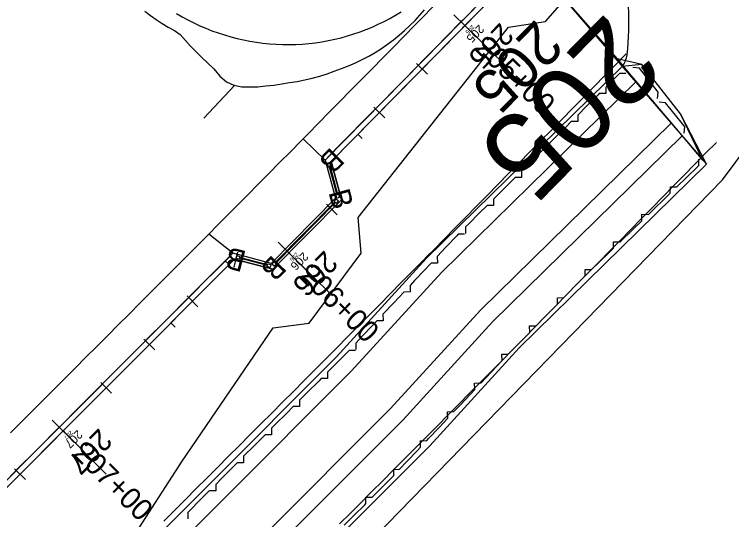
# Model space of a CAD drawing. Extents: x 1823824 to 1861612, y 706975 to 726130.
# Drawn here: x 1824906.5 to 1825141.5, y 712089.6 to 712255.1 of the extents above; entities that cross this region are included whole.
import ezdxf

# ---------------------------------------------------------------- set-up
doc = ezdxf.new("R2010")
doc.units = 0
for name, color, linetype in [('DR_X_Flood_Boundary', 7, 'Continuous'), ('GE_X_CL_10', 7, 'Continuous'), ('GE_X_CL_100', 7, 'Continuous'), ('GE_X_CL_20', 7, 'Continuous'), ('GE_X_CL_200', 7, 'Continuous'), ('GE_X_CL_50', 7, 'Continuous'), ('RW_X_Esmt_FL', 7, 'Continuous'), ('SC_Scratch1', 7, 'Continuous'), ('SC_Scratch3', 7, 'Continuous'), ('SC_Scratch5', 7, 'Continuous'), ('SC_Scratch6', 7, 'Continuous')]:
    doc.layers.add(name, color=color, linetype=linetype)

msp = doc.modelspace()

# ---------------------------------------------------------------- linework, layer by layer
at = {"layer": 'DR_X_Flood_Boundary'}
for p, q in [((1825073.72, 712271.49), (1825010.26, 712206.92)), ((1825010.26, 712206.92), (1825013.68, 712194.38)), ((1825013.68, 712194.38), (1824991.17, 712171.64)), ((1824978.6, 712174.93), (1824894.12, 712090.29)), ((1824991.17, 712171.64), (1824978.6, 712174.93))]:
    msp.add_line(p, q, dxfattribs=at)
at = {"layer": 'GE_X_CL_10'}
for p, q in [((1825054.1, 712251.52), (1825054.81, 712250.82)), ((1825019.05, 712215.86), (1825019.76, 712215.16)), ((1824996.47, 712177), (1824997.19, 712176.29)), ((1824957.78, 712154.08), (1824958.49, 712153.37)), ((1824922.46, 712118.69), (1824923.17, 712117.98))]:
    msp.add_line(p, q, dxfattribs=at)
at = {"layer": 'GE_X_CL_100'}
for p, q in [((1825054.1, 712251.52), (1825061.23, 712244.51)), ((1824996.47, 712177), (1825003.58, 712169.96)), ((1824922.46, 712118.69), (1824929.54, 712111.62))]:
    msp.add_line(p, q, dxfattribs=at)
at = {"layer": 'GE_X_CL_20'}
for p, q in [((1825054.1, 712251.52), (1825055.52, 712250.12)), ((1825019.05, 712215.86), (1825020.48, 712214.46)), ((1824996.47, 712177), (1824997.9, 712175.59)), ((1824957.78, 712154.08), (1824959.2, 712152.66)), ((1824922.46, 712118.69), (1824923.88, 712117.27))]:
    msp.add_line(p, q, dxfattribs=at)
at = {"layer": 'GE_X_CL_200'}
for p, q in [((1825054.1, 712251.52), (1825068.36, 712237.5)), ((1824996.47, 712177), (1825010.69, 712162.93)), ((1824922.46, 712118.69), (1824936.62, 712104.56))]:
    msp.add_line(p, q, dxfattribs=at)
at = {"layer": 'GE_X_CL_50'}
for p, q in [((1825054.1, 712251.52), (1825057.66, 712248.02)), ((1824996.47, 712177), (1825000.03, 712173.48)), ((1824922.46, 712118.69), (1824926, 712115.16))]:
    msp.add_line(p, q, dxfattribs=at)
at = {"layer": 'RW_X_Esmt_FL'}
for p, q in [((1825138.53, 712200.98), (1825206.62, 712292.45)), ((1824941.51, 711998.77), (1825138.53, 712200.98))]:
    msp.add_line(p, q, dxfattribs=at)
at = {"layer": 'SC_Scratch1'}
for p, q in [((1825076.76, 712271.73), (1825133.34, 712206.03)), ((1825112.07, 712238.72), (1825103.98, 712240.57)), ((1825112.07, 712238.72), (1825105.72, 712238.1)), ((1825111.3, 712237.51), (1825109.21, 712237.75)), ((1825124.81, 712222.61), (1825112.07, 712238.72)), ((1825124.81, 712222.61), (1825112.07, 712238.72)), ((1825106.87, 712235.78), (1825104.76, 712235.78)), ((1824968.54, 712221.11), (1824978.71, 712231.94)), ((1825100.28, 712231.31), (1825100.28, 712229.21)), ((1825100.28, 712229.21), (1825098.17, 712229.21)), ((1825117.26, 712227.58), (1825117.51, 712229.67)), ((1825119.92, 712226.11), (1825117.82, 712226.34)), ((1825091.09, 712222.15), (1825091.09, 712220.04)), ((1825119.63, 712222.05), (1825121.58, 712219.74)), ((1825133.34, 712206.03), (1825124.81, 712222.61)), ((1825132.11, 712207.28), (1825124.81, 712222.61)), ((1825091.09, 712220.04), (1825088.98, 712220.05)), ((1825121.58, 712219.74), (1825132.11, 712207.28)), ((1825125.97, 712216.23), (1825126.19, 712218.33)), ((1825008.3, 712207.43), (1825001.15, 712214.42)), ((1825081.9, 712212.99), (1825081.9, 712210.88)), ((1825081.9, 712210.88), (1825079.79, 712210.88)), ((1825130.76, 712205.62), (1825130.79, 712207.72)), ((1825072.71, 712203.82), (1825072.71, 712201.72)), ((1825072.71, 712201.72), (1825070.6, 712201.72)), ((1825121.44, 712196.58), (1825121.48, 712198.69)), ((1825121.48, 712198.69), (1825123.58, 712198.66)), ((1825063.52, 712192.56), (1825061.41, 712192.56)), ((1825063.52, 712194.66), (1825063.52, 712192.56)), ((1825112.13, 712187.55), (1825112.16, 712189.65)), ((1825112.16, 712189.65), (1825114.27, 712189.62)), ((1825054.33, 712185.5), (1825054.33, 712183.39)), ((1824978.07, 712176.88), (1824970.26, 712183.15)), ((1825054.01, 712183.17), (1825051.9, 712183.1)), ((1825102.81, 712178.51), (1825102.85, 712180.62)), ((1825102.85, 712180.62), (1825104.95, 712180.58)), ((1825045.07, 712175.8), (1825045.14, 712173.7)), ((1825045.14, 712173.7), (1825043.03, 712173.63)), ((1825093.55, 712169.48), (1825093.53, 712171.58)), ((1825093.53, 712171.58), (1825095.64, 712171.55)), ((1825036.17, 712166.36), (1825036.23, 712164.25)), ((1825036.23, 712164.25), (1825034.13, 712164.19)), ((1825084.44, 712162.33), (1825086.54, 712162.35)), ((1825084.46, 712160.22), (1825084.44, 712162.33)), ((1825027.27, 712156.91), (1825027.33, 712154.81)), ((1825027.33, 712154.81), (1825025.23, 712154.75)), ((1825075.34, 712153.07), (1825077.45, 712153.09)), ((1825075.36, 712150.97), (1825075.34, 712153.07)), ((1825018.37, 712147.47), (1825018.43, 712145.37)), ((1825018.27, 712145.05), (1825016.17, 712145.04)), ((1825066.23, 712143.83), (1825068.34, 712143.84)), ((1825066.3, 712141.73), (1825066.23, 712143.83)), ((1825009.13, 712137.94), (1825009.13, 712135.84)), ((1825009.13, 712135.84), (1825007.02, 712135.83)), ((1825057.33, 712134.39), (1825059.44, 712134.45)), ((1825057.39, 712132.28), (1825057.33, 712134.39)), ((1824999.96, 712128.76), (1824999.96, 712126.65)), ((1824999.96, 712126.65), (1824997.86, 712126.65)), ((1825048.43, 712124.95), (1825050.54, 712125.01)), ((1825048.49, 712122.84), (1825048.43, 712124.95)), ((1824990.79, 712117.47), (1824988.69, 712117.46)), ((1824990.79, 712119.57), (1824990.79, 712117.47)), ((1825039.53, 712115.5), (1825041.63, 712115.57)), ((1825039.59, 712113.4), (1825039.53, 712115.51)), ((1824981.62, 712110.39), (1824981.63, 712108.28)), ((1824981.63, 712108.28), (1824979.52, 712108.28)), ((1825030.59, 712106.1), (1825032.7, 712106.16)), ((1825030.85, 712104.1), (1825030.85, 712106.2)), ((1824972.46, 712101.2), (1824972.46, 712099.1)), ((1824972.46, 712099.1), (1824970.35, 712099.09)), ((1825021.68, 712094.91), (1825021.68, 712097.02)), ((1825021.68, 712097.02), (1825023.79, 712097.02)), ((1824963.29, 712092.02), (1824963.29, 712089.91))]:
    msp.add_line(p, q, dxfattribs=at)
for points in [[(1824837.54, 711922.74), (1824848.43, 711918.74), (1824860.1, 711923.16), (1824873.6, 711947.64), (1824870.6, 711959.21), (1824893.22, 711999.63), (1824920.18, 712044.82), (1824961.46, 712108.81), (1824989.89, 712150.42), (1824991.25, 712152.45), (1825003.05, 712154.01), (1825020.13, 712176.93), (1825019.11, 712188.57), (1825068.43, 712250.92), (1825080.52, 712252.77), (1825099.08, 712274.14), (1825098.5, 712286.03), (1825161.91, 712356.25)], [(1824837.54, 711922.74), (1824848.43, 711918.74), (1824860.1, 711923.16), (1824873.6, 711947.64), (1824870.6, 711959.21), (1824893.22, 711999.63), (1824920.18, 712044.82), (1824961.46, 712108.81), (1824989.89, 712150.42), (1824991.25, 712152.45), (1825003.05, 712154.01), (1825020.13, 712176.93), (1825019.11, 712188.57), (1825068.43, 712250.92), (1825080.52, 712252.77), (1825099.08, 712274.14), (1825098.5, 712286.03), (1825161.91, 712356.25)], [(1825066.18, 712280.36), (1825062.33, 712276.46), (1825058.81, 712272.91), (1825055.29, 712269.35), (1825051.78, 712265.8), (1825048.26, 712262.24), (1825044.75, 712258.69), (1825042.54, 712256.46), (1825041.23, 712255.12), (1825037.72, 712251.56), (1825034.21, 712248), (1825030.7, 712244.43), (1825027.19, 712240.87), (1825023.69, 712237.31), (1825020.18, 712233.74), (1825016.67, 712230.18), (1825013.16, 712226.62), (1825009.65, 712223.06), (1825006.15, 712219.49), (1825002.64, 712215.93), (1825001.15, 712214.42)], [(1825076.76, 712271.73), (1825103.98, 712240.57), (1825107.47, 712236.43), (1825119.63, 712222.05)], [(1824949.3, 712256.21), (1824951.08, 712254.72), (1824953.01, 712253.43), (1824954.97, 712252.19), (1824956.94, 712250.98), (1824958.94, 712249.81), (1824960.86, 712248.5), (1824962.52, 712246.6), (1824964.24, 712244.71), (1824966.04, 712242.83), (1824967.91, 712240.96), (1824969.86, 712239.11), (1824971.88, 712237.27), (1824973.83, 712234.89), (1824976.02, 712233.02), (1824978.46, 712232), (1824981.02, 712231.41), (1824983.67, 712231.43), (1824986.29, 712231.44), (1824988.92, 712231.7), (1824991.52, 712231.99), (1824994.09, 712232.36), (1824996.64, 712232.81), (1824999.16, 712233.2), (1825001.66, 712233.68), (1825004.13, 712234.27), (1825006.57, 712234.95), (1825008.97, 712235.71), (1825011.33, 712236.55), (1825013.67, 712237.39), (1825015.97, 712238.3), (1825018.23, 712239.29), (1825020.44, 712240.36), (1825022.61, 712241.49), (1825024.73, 712242.69), (1825026.79, 712243.99), (1825028.77, 712245.39), (1825030.69, 712246.84), (1825032.56, 712248.34), (1825034.37, 712249.9), (1825036.11, 712251.5), (1825037.78, 712253.18), (1825039.38, 712254.89), (1825040.92, 712256.65)], [(1824959.65, 712255.44), (1824961.5, 712254.35), (1824963.39, 712253.31), (1824965.32, 712252.34), (1824967.27, 712251.43), (1824969.24, 712250.57), (1824971.25, 712249.78), (1824973.27, 712249.05), (1824975.32, 712248.38), (1824977.39, 712247.78), (1824979.47, 712247.24), (1824981.57, 712246.76), (1824983.69, 712246.35), (1824985.81, 712246), (1824987.95, 712245.72), (1824990.09, 712245.51), (1824992.24, 712245.36), (1824994.39, 712245.27), (1824996.54, 712245.26), (1824998.7, 712245.31), (1825000.85, 712245.42), (1825002.99, 712245.61), (1825005.13, 712245.85), (1825007.26, 712246.17), (1825009.38, 712246.55), (1825011.49, 712246.99), (1825013.58, 712247.5), (1825015.66, 712248.07), (1825017.72, 712248.71), (1825019.76, 712249.41), (1825021.77, 712250.17), (1825023.76, 712250.99), (1825025.72, 712251.88), (1825027.66, 712252.82), (1825029.57, 712253.83), (1825031.44, 712254.89), (1825033.28, 712256.01)], [(1825107, 712242.22), (1825103.5, 712238.66), (1825099.99, 712235.09), (1825096.49, 712231.52), (1825092.98, 712227.96), (1825089.48, 712224.39), (1825085.97, 712220.83), (1825082.47, 712217.26), (1825078.96, 712213.69), (1825075.46, 712210.13), (1825071.95, 712206.56), (1825068.45, 712203), (1825064.94, 712199.43), (1825061.44, 712195.86), (1825057.93, 712192.3), (1825054.43, 712188.73), (1825050.92, 712185.17), (1825047.42, 712181.6), (1825043.91, 712178.03), (1825041.81, 712175.9), (1825040.3, 712174.36), (1825036.78, 712170.81), (1825033.26, 712167.26), (1825029.74, 712163.7), (1825026.23, 712160.15), (1825022.71, 712156.6), (1825019.19, 712153.04), (1825015.68, 712149.49), (1825012.16, 712145.93), (1825010.05, 712143.8), (1825008.5, 712142.25), (1825004.97, 712138.72), (1825001.44, 712135.18), (1824997.91, 712131.64), (1824994.38, 712128.1), (1824990.84, 712124.56), (1824987.31, 712121.02), (1824983.78, 712117.48), (1824980.25, 712113.94), (1824976.71, 712110.4), (1824973.18, 712106.87), (1824969.65, 712103.33), (1824966.12, 712099.79), (1824962.59, 712096.25), (1824959.05, 712092.71), (1824955.52, 712089.17)], [(1825105.72, 712238.1), (1825041.58, 712175.28), (1825012.05, 712142.98), (1824928.03, 712058.8), (1824867.42, 711988.62), (1824838.82, 711954.42), (1824791.58, 711892.69), (1824765.73, 711856.76), (1824735.96, 711811.35), (1824706.1, 711762.93), (1824677.47, 711714.29), (1824651.68, 711665.89), (1824630.67, 711625.89), (1824564.54, 711490.46), (1824542.7, 711439.44)], [(1825117.51, 712229.67), (1825117.17, 712230.09), (1825114.07, 712234.01), (1825111.3, 712237.51)], [(1825104.76, 712235.78), (1825101.33, 712232.36), (1825100.28, 712231.31)], [(1825110.13, 712232.99), (1825046.42, 712170.6), (1825016.92, 712138.33), (1824932.97, 712054.22), (1824872.55, 711984.27), (1824844.08, 711950.22), (1824796.99, 711888.68), (1824771.28, 711852.95), (1824741.64, 711807.74), (1824711.87, 711759.46), (1824683.34, 711710.99), (1824657.63, 711662.75), (1824636.68, 711622.85), (1824570.66, 711487.65), (1824551.08, 711441.92)], [(1825098.17, 712229.21), (1825097.79, 712228.83), (1825094.25, 712225.3), (1825091.09, 712222.15)], [(1825126.19, 712218.33), (1825125.86, 712218.74), (1825122.72, 712222.64), (1825119.92, 712226.11)], [(1825121.76, 712219.53), (1825059.19, 712158.26), (1825029.76, 712126.06), (1824945.98, 712042.13), (1824886.07, 711972.77), (1824857.94, 711939.13), (1824811.24, 711878.1), (1824785.91, 711842.89), (1824756.62, 711798.22), (1824727.07, 711750.3), (1824698.83, 711702.31), (1824673.32, 711654.44), (1824652.51, 711614.83), (1824615.99, 711540.02)], [(1825088.98, 712220.05), (1825087.17, 712218.24), (1825083.63, 712214.71), (1825081.9, 712212.99)], [(1825125.32, 712215.32), (1825063.14, 712154.44), (1825033.74, 712122.26), (1824950.02, 712038.39), (1824890.27, 711969.21), (1824862.23, 711935.69), (1824815.66, 711874.82), (1824790.44, 711839.78), (1824761.26, 711795.26), (1824731.78, 711747.46), (1824703.63, 711699.63), (1824678.18, 711651.87), (1824657.42, 711612.34), (1824626.24, 711548.48)], [(1825001.15, 712214.42), (1825000.45, 712213.71), (1824996.93, 712210.15), (1824993.41, 712206.6), (1824989.9, 712203.05), (1824986.38, 712199.49), (1824982.86, 712195.94), (1824979.35, 712192.38), (1824975.83, 712188.83), (1824972.31, 712185.28), (1824971.07, 712184.03), (1824968.8, 712181.75), (1824965.27, 712178.21), (1824961.74, 712174.67), (1824958.2, 712171.13), (1824954.67, 712167.59), (1824951.14, 712164.05), (1824947.61, 712160.51), (1824944.07, 712156.98), (1824940.54, 712153.44), (1824937.01, 712149.9), (1824933.48, 712146.36), (1824929.95, 712142.82), (1824926.41, 712139.28), (1824922.88, 712135.74), (1824919.35, 712132.2), (1824915.82, 712128.66), (1824912.29, 712125.12), (1824908.75, 712121.59), (1824905.22, 712118.05)], [(1825052.13, 712127.47), (1825055.65, 712131.02), (1825059.17, 712134.58), (1825062.69, 712138.13), (1825066.2, 712141.69), (1825069.72, 712145.24), (1825071.34, 712146.88), (1825073.44, 712149.01), (1825076.95, 712152.58), (1825080.45, 712156.15), (1825083.96, 712159.71), (1825087.46, 712163.28), (1825090.96, 712166.84), (1825094.47, 712170.41), (1825097.97, 712173.98), (1825101.48, 712177.54), (1825104.98, 712181.11), (1825108.49, 712184.67), (1825111.99, 712188.24), (1825115.5, 712191.81), (1825119, 712195.37), (1825122.51, 712198.94), (1825126.01, 712202.5), (1825129.52, 712206.07), (1825133.02, 712209.64), (1825136.53, 712213.2)], [(1825079.79, 712210.88), (1825076.55, 712207.65), (1825073.01, 712204.12), (1825072.71, 712203.82)], [(1825133.34, 712206.03), (1825071.96, 712145.93), (1825042.6, 712113.8), (1824959, 712030.04), (1824899.6, 711961.27), (1824871.8, 711928.03), (1824825.5, 711867.52), (1824800.54, 711832.84), (1824771.6, 711788.69), (1824742.28, 711741.14), (1824714.32, 711693.64), (1824689.01, 711646.14), (1824668.35, 711606.81), (1824642.05, 711552.94)], [(1825123.58, 712198.66), (1825126.74, 712201.72), (1825130.33, 712205.2), (1825130.76, 712205.62)], [(1825070.6, 712201.72), (1825069.47, 712200.59), (1825065.93, 712197.06), (1825063.52, 712194.66)], [(1825114.27, 712189.62), (1825115.97, 712191.27), (1825119.56, 712194.76), (1825121.44, 712196.58)], [(1825061.41, 712192.56), (1825058.85, 712190), (1825055.3, 712186.47), (1825054.33, 712185.5)], [(1825104.95, 712180.58), (1825105.21, 712180.83), (1825108.79, 712184.31), (1825112.13, 712187.55)], [(1825051.9, 712183.1), (1825051.46, 712182.63), (1825048.04, 712178.98), (1825045.07, 712175.8)], [(1825095.64, 712171.55), (1825098.03, 712173.87), (1825101.62, 712177.35), (1825102.81, 712178.51)], [(1824978.07, 712176.88), (1824975.88, 712174.68), (1824972.35, 712171.14), (1824968.81, 712167.61), (1824965.28, 712164.07), (1824961.75, 712160.53), (1824958.22, 712156.99), (1824954.68, 712153.45), (1824951.15, 712149.91), (1824947.62, 712146.37), (1824944.09, 712142.83), (1824940.56, 712139.29), (1824937.02, 712135.76), (1824933.49, 712132.22), (1824929.96, 712128.68), (1824926.43, 712125.14), (1824922.9, 712121.6), (1824919.36, 712118.06), (1824915.83, 712114.52), (1824912.3, 712110.98), (1824908.77, 712107.44), (1824905.23, 712103.9)], [(1825043.03, 712173.63), (1825042.58, 712173.14), (1825041.1, 712171.57), (1825037.66, 712167.94), (1825036.17, 712166.36)], [(1825086.54, 712162.35), (1825087.46, 712163.28), (1825090.96, 712166.84), (1825093.55, 712169.48)], [(1825034.13, 712164.19), (1825030.8, 712160.66), (1825027.37, 712157.02), (1825027.27, 712156.91)], [(1825077.45, 712153.09), (1825080.45, 712156.15), (1825083.96, 712159.71), (1825084.46, 712160.22)], [(1825025.23, 712154.75), (1825023.94, 712153.39), (1825020.51, 712149.75), (1825018.37, 712147.47)], [(1825068.34, 712143.84), (1825069.72, 712145.24), (1825071.34, 712146.88), (1825073.44, 712149.01), (1825075.36, 712150.97)], [(1825016.17, 712145.04), (1825013.43, 712142.27), (1825011.32, 712140.14), (1825009.77, 712138.59), (1825009.13, 712137.94)], [(1825059.44, 712134.45), (1825062.83, 712138.05), (1825066.26, 712141.68), (1825066.3, 712141.73)], [(1825007.02, 712135.83), (1825006.24, 712135.05), (1825002.71, 712131.51), (1824999.96, 712128.76)], [(1825050.54, 712125.01), (1825052.54, 712127.13), (1825055.97, 712130.77), (1825057.39, 712132.28)], [(1825013.08, 712088.23), (1825016.61, 712091.77), (1825020.14, 712095.31), (1825023.68, 712098.85), (1825027.21, 712102.39), (1825030.74, 712105.93), (1825034.27, 712109.47), (1825037.81, 712113.01), (1825039.48, 712114.68), (1825041.58, 712116.81), (1825045.1, 712120.36), (1825048.62, 712123.92), (1825052.13, 712127.47)], [(1824997.86, 712126.65), (1824995.65, 712124.43), (1824992.11, 712120.9), (1824990.79, 712119.57)], [(1825041.63, 712115.57), (1825042.25, 712116.22), (1825045.68, 712119.86), (1825048.49, 712122.84)], [(1824988.69, 712117.46), (1824988.58, 712117.36), (1824985.05, 712113.82), (1824981.62, 712110.39)], [(1825032.7, 712106.16), (1825035.12, 712108.7), (1825038.56, 712112.32), (1825039.59, 712113.4)], [(1824979.52, 712108.28), (1824977.99, 712106.74), (1824974.45, 712103.2), (1824972.46, 712101.2)], [(1825023.79, 712097.02), (1825024.84, 712098.08), (1825028.37, 712101.61), (1825030.85, 712104.1)], [(1824970.35, 712099.09), (1824967.39, 712096.12), (1824963.86, 712092.58), (1824963.29, 712092.02)], [(1825014.62, 712087.84), (1825017.77, 712091), (1825021.3, 712094.54), (1825021.68, 712094.91)]]:
    msp.add_lwpolyline(points, dxfattribs=at)
for centre, radius, start, end in [((1824999.17, 712252.81), 108.74, 354.2399, 2.6127), ((1825097.04, 712244.09), 10.55, 325.4095, 348.0046)]:
    msp.add_arc(centre, radius, start, end, dxfattribs=at)
at = {"layer": 'SC_Scratch3'}
for p, q in [((1825012.01, 712208.7), (1825010.76, 712209.93)), ((1825010.03, 712206.33), (1825009.06, 712206.07)), ((1825009.06, 712206.07), (1825009.32, 712205.11)), ((1825009.32, 712205.11), (1825010.29, 712205.37)), ((1825009.69, 712205.2), (1825012.19, 712196.05)), ((1825009.93, 712205.27), (1825012.43, 712196.11)), ((1825010.29, 712205.37), (1825010.03, 712206.33)), ((1825012.79, 712196.21), (1825011.83, 712195.95)), ((1825011.83, 712195.95), (1825012.09, 712194.98)), ((1825012.09, 712194.98), (1825013.06, 712195.25)), ((1825013.06, 712195.25), (1825012.79, 712196.21)), ((1825011.56, 712193.66), (1824991.87, 712173.76)), ((1825011.74, 712193.49), (1824992.05, 712173.59)), ((1825012, 712194.64), (1825011.3, 712193.93)), ((1825011.3, 712193.93), (1825012.01, 712193.22)), ((1825012.71, 712193.94), (1825012, 712194.64)), ((1825012.01, 712193.22), (1825012.71, 712193.94)), ((1825006.76, 712188.45), (1825006.58, 712188.63)), ((1825006.88, 712188.57), (1825006.7, 712188.75)), ((1825001.83, 712183.48), (1825001.66, 712183.65)), ((1825001.95, 712183.6), (1825001.77, 712183.77)), ((1824996.91, 712178.5), (1824996.73, 712178.68)), ((1824997.03, 712178.62), (1824996.85, 712178.8)), ((1824979.18, 712175.17), (1824979.44, 712176.13)), ((1824979.44, 712176.13), (1824980.4, 712175.88)), ((1824976.83, 712173.16), (1824975.59, 712174.4)), ((1824980.15, 712174.91), (1824979.18, 712175.17)), ((1824980.4, 712175.88), (1824980.15, 712174.91)), ((1824989.43, 712172.87), (1824980.24, 712175.27)), ((1824989.49, 712173.11), (1824980.31, 712175.52)), ((1824990.9, 712173.31), (1824991.6, 712174.03)), ((1824991.6, 712174.03), (1824992.31, 712173.32)), ((1824989.33, 712172.51), (1824989.59, 712173.47)), ((1824990.3, 712172.25), (1824989.33, 712172.51)), ((1824989.59, 712173.47), (1824990.55, 712173.22)), ((1824990.55, 712173.22), (1824990.3, 712172.25)), ((1824991.61, 712172.61), (1824990.9, 712173.31)), ((1824992.31, 712173.32), (1824991.61, 712172.61))]:
    msp.add_line(p, q, dxfattribs=at)
for points in [[(1825072.21, 712272.45), (1825008.3, 712207.43), (1825011.73, 712194.9), (1824990.64, 712173.59), (1824978.07, 712176.88), (1824892.84, 712091.49), (1824830.41, 712019.21), (1824830.77, 712007.17), (1824813.65, 711986.72), (1824801.74, 711984.95), (1824752.63, 711920.76), (1824753.86, 711908.78), (1824738.28, 711887.14), (1824726.53, 711884.51), (1824695.45, 711837.1), (1824665, 711787.73)], [(1824666.49, 711786.8), (1824696.93, 711836.18), (1824727.6, 711882.96), (1824739.31, 711885.58), (1824755.67, 711908.3), (1824754.44, 711920.25), (1824802.7, 711983.32), (1824814.57, 711985.09), (1824832.54, 712006.56), (1824832.18, 712018.58), (1824894.12, 712090.29), (1824978.6, 712174.93), (1824991.17, 712171.64), (1825013.68, 712194.38), (1825010.26, 712206.92), (1825073.72, 712271.49)], [(1825072.32, 712272.35), (1825069.44, 712269.43), (1825065.92, 712265.88), (1825062.4, 712262.32), (1825058.89, 712258.77), (1825055.37, 712255.21), (1825051.86, 712251.66), (1825049.65, 712249.42), (1825048.35, 712248.11), (1825044.84, 712244.54), (1825041.34, 712240.98), (1825037.83, 712237.42), (1825034.32, 712233.85), (1825030.81, 712230.29), (1825027.3, 712226.73), (1825023.8, 712223.17), (1825020.29, 712219.6), (1825016.78, 712216.04), (1825013.27, 712212.48), (1825009.76, 712208.91), (1825008.3, 712207.43)]]:
    msp.add_lwpolyline(points, dxfattribs=at)
at = {"layer": 'SC_Scratch5'}
for points in [[(1825057.66, 712248.02), (1825050.53, 712255.03)], [(1825041.86, 712235.51), (1825038.3, 712239.01)], [(1825027.84, 712221.24), (1825024.28, 712224.75)], [(1825013.82, 712206.98), (1825010.26, 712210.48)], [(1825012.32, 712189.45), (1825008.77, 712192.97)], [(1825000.03, 712173.48), (1824992.92, 712180.51)], [(1824978.48, 712172.38), (1824979.75, 712177.21)], [(1824966.62, 712159.39), (1824963.08, 712162.92)], [(1824952.49, 712145.23), (1824948.95, 712148.76)], [(1824938.36, 712131.08), (1824934.82, 712134.61)], [(1824926, 712115.16), (1824918.92, 712122.22)], [(1824910.1, 712102.77), (1824906.56, 712106.3)]]:
    msp.add_lwpolyline(points, dxfattribs=at)

# ---------------------------------------------------------------- texts
at = {"layer": 'GE_X_CL_10'}
for s, rotation, p in [('205', 225.4954, (1825056.43, 712251.76)), ('206', 225.3001, (1824998.81, 712177.23)), ('207', 225.0545, (1824924.82, 712118.93))]:
    msp.add_text(s, height=1.4, rotation=rotation, dxfattribs=at).set_placement(p)
at = {"layer": 'GE_X_CL_100'}
msp.add_text('205', height=14, rotation=225.4954, dxfattribs=at).set_placement((1825077.43, 712253.86))
at = {"layer": 'GE_X_CL_20'}
for s, rotation, p in [('205', 225.4954, (1825058.76, 712251.99)), ('206', 225.3001, (1825001.15, 712177.45)), ('207', 225.0545, (1824927.18, 712119.17))]:
    msp.add_text(s, height=2.8, rotation=rotation, dxfattribs=at).set_placement(p)
at = {"layer": 'GE_X_CL_200'}
msp.add_text('205', height=28, rotation=225.4954, dxfattribs=at).set_placement((1825100.76, 712256.2))
at = {"layer": 'GE_X_CL_50'}
for s, rotation, p in [('205', 225.4954, (1825065.76, 712252.69)), ('206', 225.3001, (1825008.16, 712178.14)), ('207', 225.0545, (1824934.25, 712119.88))]:
    msp.add_text(s, height=7, rotation=rotation, dxfattribs=at).set_placement(p)
at = {"layer": 'SC_Scratch5'}
for s, rotation, p in [('205+00', 315.4954, (1825056.99, 712243.77)), ('206+00', 315.3001, (1824999.34, 712169.23)), ('207+00', 315.0545, (1824925.3, 712110.91))]:
    msp.add_text(s, height=7, rotation=rotation, dxfattribs=at).set_placement(p)
at = {"layer": 'SC_Scratch6'}
for rotation, p in [(225.4954, (1825010.21, 712211.87)), (285.2845, (1825009.38, 712196.84)), (165.319, (1824982.87, 712177.43)), (225.3001, (1824991.15, 712176.59))]:
    msp.add_text('B', height=7, rotation=rotation, dxfattribs=at).set_placement(p)

doc.saveas('drawing.dxf')
